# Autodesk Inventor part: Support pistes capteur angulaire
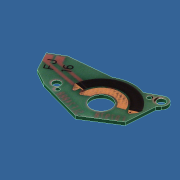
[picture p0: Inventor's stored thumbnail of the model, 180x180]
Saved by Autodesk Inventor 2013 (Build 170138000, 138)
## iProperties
Created: 2011-10
Part Number: Support pistes capteur angulaire
Document SubType Name: Modeling
Designer: Laur
Density: 1.38 g/cm^3
Material: Phénolique
Mass: 0.273708 g
Surface Area: 5.80607 cm^2
Volume: 0.198339 cm^3
Author: Laur
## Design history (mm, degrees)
sketch "Esquisse1"
  geometry: L1 (0.778, 16.859)-(29.221, 16.848); L2 (29.221, 16.848)-(29.214, 0.201); L3 (29.214, 0.201)-(0.771, 0.212); L4 (0.771, 0.212)-(0.778, 16.859); L5 (4.832, 12.902)-(1.158, 10.769); L6 (1.158, 10.769)-(3.898, 5.676); L7 (3.898, 5.676)-(7.958, 3.405); L8 (7.958, 3.405)-(19.495, 0.204); L9 (19.495, 0.204)-(27.58, 5.328); L10 (27.58, 5.328)-(28.116, 12.877); L11 (4.832, 12.902)-(15.629, 13.919); L12 (23.157, 14.511)-(26.7, 16.404); L13 (9.603, 5.142)-(27.685, 14.8); L14 (0, -3.458)-(0, 20.746) reference; L15 (-5.987, 0)-(35.921, 0) reference; L16 (28.116, 12.877)-(28.854, 13.774); C1 r 2.65 at (20, 6.5); C2 r 1 at (27.685, 14.8); C3 r 0.5 at (25.2, 14.1); C4 r 1 at (9.603, 5.142); C5 r 0.5 at (11.1, 3.9); A1 r 8.611 centre (20, 6.5) between (23.157, 14.511) and (15.629, 13.919); A2 r 1.733 centre (27.517, 14.876) between (28.854, 13.774) and (26.7, 16.404); 1 further point; 1 other entity
  constraints: 20 end point, 7 centre point, 4 point on circle, 2 coincident, 2 tangent, 1 parallel, 1 point on line, 3 other
  dimensions: "d9" = 5.3 diameter of C1; "d30" = 1 diameter of C3; "d31" = 2 diameter of C2; "d32" = 2 diameter of C4; "d33" = 1 diameter of C5; "d37" = 8.9 horizontal distance of C1.centre C5.centre; "d39" = 2.6 vertical distance of C5.centre C1.centre; "d40" = 7.6 vertical distance of C3.centre A1.centre; "d42" = 5.2 horizontal distance of C1.centre C3.centre; "d81" = 8.3 vertical distance of A1.centre C2.centre; "d189" = 10.485 distance of L13.start C1.centre; "d192" = 20.5 distance of C2.centre L13.start; "d249" = 3.7 distance from line of C1.centre L13; "d264" = 20 horizontal distance of point (0, 0) C1.centre; "d265" = 6.50048 vertical distance of point (0, 0) C1.centre; "d335" = 0.022187 deg angle of L3 L15 (derived); "d337" = 0.8 distance of L3.end point (0, 0)
  node "Image3"
extrude "Extrusion1" new body sketch "Esquisse1" distance "d99" = 0.8; taper "d100" = 0 deg
feature "Décalcomanie1"
sketch "Esquisse2"
  geometry: L1 (3.115, -7.489)-(-35.416, -5.384); L2 (-35.416, -5.384)-(-33.837, 23.514); L3 (-33.837, 23.514)-(4.693, 21.409); L4 (4.693, 21.409)-(3.115, -7.489); 1 other entity
  constraints: 2 other
feature "Décalcomanie2" sketch "Esquisse2"
node "Solide1"
node "Corps solides"
node "Corps surfaciques"
node "Image6"
other parameters: "d29" = 17
